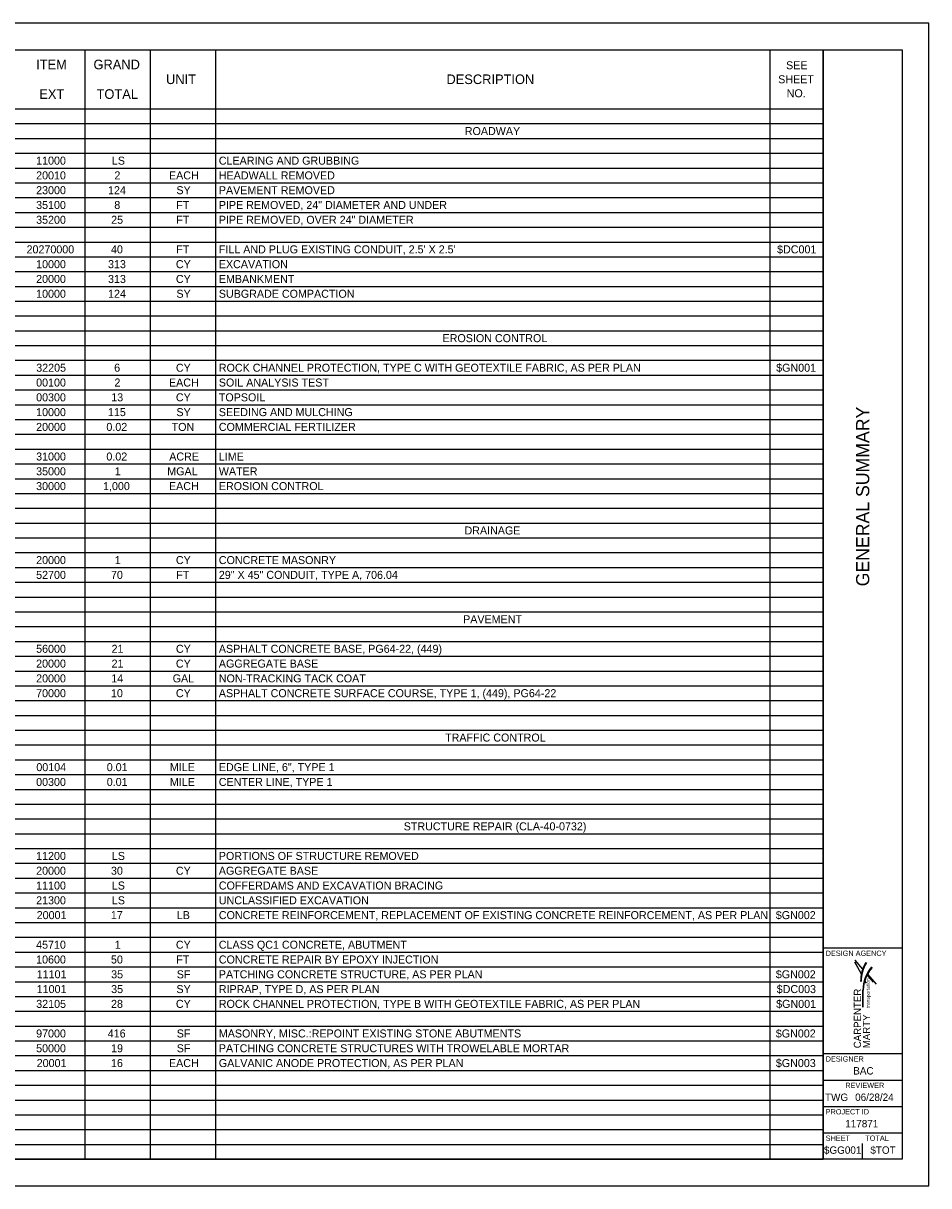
# Model space of a CAD drawing. Extents: x 0 to 34, y 0 to 22.
# Drawn here: x 16.87 to 34, y 0 to 22 of the extents above; entities that cross this region are included whole.
import ezdxf

# ---------------------------------------------------------------- set-up
doc = ezdxf.new("R2010")
doc.units = 0
for name, color, linetype in [('SH_Border', 7, 'Continuous'), ('SH_Cut_Line', 7, 'Continuous'), ('SH_Data', 7, 'Continuous'), ('SH_Text', 7, 'Continuous')]:
    doc.layers.add(name, color=color, linetype=linetype)

msp = doc.modelspace()

# ---------------------------------------------------------------- linework, layer by layer
at = {"layer": 'SH_Border'}
for p, q in [((32, 0.5), (32, 21.5)), ((32, 4.5), (33.5, 4.5)), ((32, 2.5), (33.5, 2.5)), ((32, 2), (33.5, 2)), ((32, 1.5), (33.5, 1.5)), ((32, 1), (33.5, 1))]:
    msp.add_line(p, q, dxfattribs=at)
msp.add_lwpolyline([(1.5, 21.5), (33.5, 21.5), (33.5, 0.5), (1.5, 0.5)], close=True, dxfattribs=at)
at = {"layer": 'SH_Cut_Line'}
msp.add_lwpolyline([(0, 0), (34, 0), (34, 22), (0, 22)], close=True, dxfattribs=at)
at = {"layer": 'SH_Data'}
for p, q in [((32.75, 3.5), (32.75, 3.5)), ((32.375, 0.675), (32.375, 0.675)), ((32.75, 0.5), (32.75, 0.8))]:
    msp.add_line(p, q, dxfattribs=at)
at = {"layer": 'SH_Text'}
for p, q in [((1.5, 21.5), (32, 21.5)), ((18.035, 21.5), (18.035, 0.502)), ((19.27, 21.5), (19.27, 0.502)), ((20.505, 21.5), (20.505, 0.502)), ((30.995, 21.5), (30.995, 0.502)), ((32, 21.5), (32, 0.502)), ((1.5, 20.38), (32, 20.38)), ((1.5, 20.1), (32, 20.1)), ((1.5, 19.82), (32, 19.82)), ((1.5, 19.54), (32, 19.54)), ((1.5, 19.26), (32, 19.26)), ((1.5, 18.98), (32, 18.98)), ((1.5, 18.7), (32, 18.7)), ((1.5, 18.42), (32, 18.42)), ((1.5, 18.14), (32, 18.14)), ((1.5, 17.86), (32, 17.86)), ((1.5, 17.58), (32, 17.58)), ((1.5, 17.3), (32, 17.3)), ((1.5, 17.021), (32, 17.021)), ((1.5, 16.741), (32, 16.741)), ((1.5, 16.461), (32, 16.461)), ((1.5, 16.181), (32, 16.181)), ((1.5, 15.901), (32, 15.901)), ((1.5, 15.621), (32, 15.621)), ((1.5, 15.341), (32, 15.341)), ((1.5, 15.061), (32, 15.061)), ((1.5, 14.781), (32, 14.781)), ((1.5, 14.501), (32, 14.501)), ((1.5, 14.221), (32, 14.221)), ((1.5, 13.941), (32, 13.941)), ((1.5, 13.661), (32, 13.661)), ((1.5, 13.381), (32, 13.381)), ((1.5, 13.101), (32, 13.101)), ((1.5, 12.821), (32, 12.821)), ((1.5, 12.541), (32, 12.541)), ((1.5, 12.261), (32, 12.261)), ((1.5, 11.981), (32, 11.981)), ((1.5, 11.701), (32, 11.701)), ((1.5, 11.421), (32, 11.421)), ((1.5, 11.141), (32, 11.141)), ((1.5, 10.861), (32, 10.861)), ((1.5, 10.581), (32, 10.581)), ((1.5, 10.301), (32, 10.301)), ((1.5, 10.021), (32, 10.021)), ((1.5, 9.741), (32, 9.741)), ((1.5, 9.461), (32, 9.461)), ((1.5, 9.181), (32, 9.181)), ((1.5, 8.901), (32, 8.901)), ((1.5, 8.621), (32, 8.621)), ((1.5, 8.342), (32, 8.342)), ((1.5, 8.062), (32, 8.062)), ((1.5, 7.782), (32, 7.782)), ((1.5, 7.502), (32, 7.502)), ((1.5, 7.222), (32, 7.222)), ((1.5, 6.942), (32, 6.942)), ((1.5, 6.662), (32, 6.662)), ((1.5, 6.382), (32, 6.382)), ((1.5, 6.102), (32, 6.102)), ((1.5, 5.822), (32, 5.822)), ((1.5, 5.542), (32, 5.542)), ((1.5, 5.262), (32, 5.262)), ((1.5, 4.982), (32, 4.982)), ((1.5, 4.702), (32, 4.702)), ((1.5, 4.422), (32, 4.422)), ((32.721, 4.016), (32.602, 4.232)), ((1.5, 4.142), (32, 4.142)), ((32.952, 3.853), (32.834, 3.991)), ((32.839, 4.002), (33.006, 3.816)), ((1.5, 3.862), (32, 3.862)), ((32.811, 3.84), (32.79, 3.88)), ((32.82, 3.834), (32.791, 3.886)), ((1.5, 3.582), (32, 3.582)), ((32.755, 3.378), (32.755, 3.704)), ((32.762, 3.378), (32.762, 3.704)), ((1.5, 3.302), (32, 3.302)), ((1.5, 3.022), (32, 3.022)), ((1.5, 2.742), (32, 2.742)), ((1.5, 2.462), (32, 2.462)), ((1.5, 2.182), (32, 2.182)), ((1.5, 1.902), (32, 1.902)), ((1.5, 1.622), (32, 1.622)), ((1.5, 1.342), (32, 1.342)), ((1.5, 1.062), (32, 1.062)), ((1.5, 0.782), (32, 0.782)), ((1.5, 0.502), (32, 0.502))]:
    msp.add_line(p, q, dxfattribs=at)
for points in [[(32.746, 4.104), (32.601, 4.266)], [(32.601, 4.266), (32.744, 4.098)], [(32.721, 4.016), (32.602, 4.232)], [(32.602, 4.232), (32.719, 4.011)]]:
    msp.add_lwpolyline(points, dxfattribs=at)
for centre, radius, start, end in [((33.432, 3.86), 0.721, 149.5704, 179.5529), ((33.373, 3.862), 0.654, 147.1423, 179.6525), ((33.426, 3.704), 0.671, 139.2898, 180.0106), ((33.433, 3.688), 0.672, 138.5126, 178.6075)]:
    msp.add_arc(centre, radius, start, end, dxfattribs=at)

# ---------------------------------------------------------------- texts
at = {"layer": 'SH_Data'}
msp.add_text('GENERAL SUMMARY', height=0.25, rotation=90, dxfattribs=at).set_placement((32.875, 11.344))
for s, height, p in [('DESIGN AGENCY', 0.1, (32.05, 4.35)), ('DESIGNER', 0.1, (32.05, 2.35)), ('BAC', 0.14, (32.572, 2.105)), ('REVIEWER', 0.1, (32.422, 1.85)), ('TWG', 0.14, (32.038, 1.605)), ('06/28/24', 0.14, (32.608, 1.605)), ('PROJECT ID', 0.1, (32.05, 1.35)), ('117871', 0.14, (32.421, 1.105)), ('SHEET', 0.1, (32.05, 0.85)), ('TOTAL', 0.1, (32.8, 0.85)), ('$GG001', 0.14, (32.018, 0.605)), ('$TOT', 0.14, (32.896, 0.605))]:
    msp.add_text(s, height=height, dxfattribs=at).set_placement(p)
at = {"layer": 'SH_Text'}
for s, height, p in [('ITEM', 0.1818, (17.115, 21.129)), ('GRAND', 0.1818, (18.2, 21.129)), ('SEE ', 0.1515, (31.301, 21.129)), ('UNIT', 0.1818, (19.573, 20.849)), ('DESCRIPTION', 0.18181, (24.877, 20.849)), ('SHEET ', 0.1515, (31.152, 20.864)), ('EXT', 0.1818, (17.175, 20.569)), ('TOTAL', 0.1818, (18.258, 20.569)), ('NO.', 0.1515, (31.313, 20.599)), ('ROADWAY', 0.1515, (25.224, 19.884)), ('11000', 0.1515, (17.115, 19.324)), ('LS', 0.1515, (18.548, 19.324)), ('CLEARING AND GRUBBING', 0.15151, (20.571, 19.324)), ('20010', 0.1515, (17.115, 19.045)), ('2', 0.152, (18.596, 19.045)), ('EACH', 0.1515, (19.628, 19.045)), ('HEADWALL REMOVED', 0.15151, (20.571, 19.045)), ('23000', 0.1515, (17.115, 18.765)), ('124', 0.1515, (18.475, 18.765)), ('SY', 0.1515, (19.769, 18.765)), ('PAVEMENT REMOVED', 0.15151, (20.571, 18.765)), ('35100', 0.1515, (17.115, 18.485)), ('8', 0.152, (18.593, 18.485)), ('FT', 0.1515, (19.766, 18.485)), ('PIPE REMOVED, 24" DIAMETER AND UNDER', 0.15151, (20.571, 18.485)), ('35200', 0.1515, (17.115, 18.205)), ('25', 0.1515, (18.534, 18.205)), ('FT', 0.1515, (19.766, 18.205)), ('PIPE REMOVED, OVER 24" DIAMETER', 0.15151, (20.571, 18.205)), ('20270000', 0.1515, (16.934, 17.645)), ('40', 0.1515, (18.531, 17.645)), ('FT', 0.1515, (19.766, 17.645)), ("FILL AND PLUG EXISTING CONDUIT, 2.5' X 2.5'", 0.15151, (20.571, 17.645)), ('$DC001', 0.1515, (31.131, 17.645)), ('10000', 0.1515, (17.115, 17.365)), ('313', 0.1515, (18.475, 17.365)), ('CY', 0.1515, (19.759, 17.365)), ('EXCAVATION', 0.1515, (20.571, 17.365)), ('20000', 0.1515, (17.115, 17.085)), ('313', 0.1515, (18.475, 17.085)), ('CY', 0.1515, (19.759, 17.085)), ('EMBANKMENT', 0.1515, (20.571, 17.085)), ('10000', 0.1515, (17.115, 16.805)), ('124', 0.1515, (18.475, 16.805)), ('SY', 0.1515, (19.769, 16.805)), ('SUBGRADE COMPACTION', 0.15151, (20.571, 16.805)), ('EROSION CONTROL', 0.15151, (24.803, 15.965)), ('32205', 0.1515, (17.117, 15.405)), ('6', 0.152, (18.591, 15.405)), ('CY', 0.1515, (19.759, 15.405)), ('ROCK CHANNEL PROTECTION, TYPE C WITH GEOTEXTILE FABRIC, AS PER PLAN', 0.15151, (20.571, 15.405)), ('$GN001', 0.1515, (31.114, 15.405)), ('00100', 0.1515, (17.115, 15.125)), ('2', 0.152, (18.596, 15.125)), ('EACH', 0.1515, (19.628, 15.125)), ('SOIL ANALYSIS TEST', 0.15151, (20.571, 15.125)), ('00300', 0.1515, (17.115, 14.845)), ('13', 0.1515, (18.536, 14.845)), ('CY', 0.1515, (19.759, 14.845)), ('TOPSOIL', 0.1515, (20.571, 14.845)), ('10000', 0.1515, (17.115, 14.565)), ('115', 0.1515, (18.473, 14.565)), ('SY', 0.1515, (19.769, 14.565)), ('SEEDING AND MULCHING', 0.15151, (20.571, 14.565)), ('20000', 0.1515, (17.115, 14.285)), ('0.02', 0.1515, (18.444, 14.285)), ('TON', 0.1515, (19.678, 14.285)), ('COMMERCIAL FERTILIZER', 0.15151, (20.571, 14.285)), ('31000', 0.1515, (17.115, 13.725)), ('0.02', 0.1515, (18.444, 13.725)), ('ACRE', 0.1515, (19.633, 13.725)), ('LIME', 0.1515, (20.571, 13.725)), ('35000', 0.1515, (17.115, 13.445)), ('1', 0.152, (18.603, 13.445)), ('MGAL', 0.1515, (19.596, 13.445)), ('WATER', 0.1515, (20.571, 13.445)), ('30000', 0.1515, (17.115, 13.165)), ('1,000', 0.1515, (18.381, 13.165)), ('EACH', 0.1515, (19.628, 13.165)), ('EROSION CONTROL', 0.15151, (20.571, 13.165)), ('DRAINAGE', 0.1515, (25.218, 12.325)), ('20000', 0.1515, (17.115, 11.765)), ('1', 0.152, (18.603, 11.765)), ('CY', 0.1515, (19.759, 11.765)), ('CONCRETE MASONRY', 0.15151, (20.571, 11.765)), ('52700', 0.1515, (17.115, 11.485)), ('70', 0.1515, (18.531, 11.485)), ('FT', 0.1515, (19.766, 11.485)), ('29" X 45" CONDUIT, TYPE A, 706.04', 0.15151, (20.571, 11.485)), ('PAVEMENT', 0.1515, (25.192, 10.645)), ('56000', 0.1515, (17.115, 10.086)), ('21', 0.1515, (18.542, 10.086)), ('CY', 0.1515, (19.759, 10.086)), ('ASPHALT CONCRETE BASE, PG64-22, (449)', 0.15151, (20.571, 10.086)), ('20000', 0.1515, (17.115, 9.806)), ('21', 0.1515, (18.542, 9.806)), ('CY', 0.1515, (19.759, 9.806)), ('AGGREGATE BASE', 0.15151, (20.571, 9.806)), ('20000', 0.1515, (17.115, 9.526)), ('14', 0.1515, (18.536, 9.526)), ('GAL', 0.1515, (19.698, 9.526)), ('NON-TRACKING TACK COAT', 0.15151, (20.571, 9.526)), ('70000', 0.1515, (17.115, 9.246)), ('10', 0.1515, (18.531, 9.246)), ('CY', 0.1515, (19.759, 9.246)), ('ASPHALT CONCRETE SURFACE COURSE, TYPE 1, (449), PG64-22', 0.15151, (20.571, 9.246)), ('TRAFFIC CONTROL', 0.15151, (24.851, 8.406)), ('00104', 0.1515, (17.119, 7.846)), ('0.01', 0.1515, (18.451, 7.846)), ('MILE', 0.1515, (19.645, 7.846)), ('EDGE LINE, 6", TYPE 1', 0.15151, (20.571, 7.846)), ('00300', 0.1515, (17.115, 7.566)), ('0.01', 0.1515, (18.451, 7.566)), ('MILE', 0.1515, (19.645, 7.566)), ('CENTER LINE, TYPE 1', 0.15151, (20.571, 7.566)), ('STRUCTURE REPAIR (CLA-40-0732)', 0.15151, (24.068, 6.726)), ('11200', 0.1515, (17.115, 6.166)), ('LS', 0.1515, (18.548, 6.166)), ('PORTIONS OF STRUCTURE REMOVED', 0.15151, (20.571, 6.166)), ('20000', 0.1515, (17.115, 5.886)), ('30', 0.1515, (18.531, 5.886)), ('CY', 0.1515, (19.759, 5.886)), ('AGGREGATE BASE', 0.15151, (20.571, 5.886)), ('11100', 0.1515, (17.115, 5.606)), ('LS', 0.1515, (18.548, 5.606)), ('COFFERDAMS AND EXCAVATION BRACING', 0.15151, (20.571, 5.606)), ('21300', 0.1515, (17.115, 5.326)), ('LS', 0.1515, (18.548, 5.326)), ('UNCLASSIFIED EXCAVATION', 0.15151, (20.571, 5.326)), ('20001', 0.1515, (17.126, 5.046)), ('17', 0.1515, (18.528, 5.046)), ('LB', 0.1515, (19.776, 5.046)), ('CONCRETE REINFORCEMENT, REPLACEMENT OF EXISTING CONCRETE REINFORCEMENT, AS PER PLAN', 0.15151, (20.571, 5.046)), ('$GN002', 0.1515, (31.107, 5.046)), ('45710', 0.1515, (17.115, 4.486)), ('1', 0.152, (18.603, 4.486)), ('CY', 0.1515, (19.759, 4.486)), ('CLASS QC1 CONCRETE, ABUTMENT', 0.15151, (20.571, 4.486)), ('10600', 0.1515, (17.115, 4.206)), ('50', 0.1515, (18.531, 4.206)), ('FT', 0.1515, (19.766, 4.206)), ('CONCRETE REPAIR BY EPOXY INJECTION', 0.15151, (20.571, 4.206)), ('11101', 0.1515, (17.126, 3.926)), ('35', 0.1515, (18.534, 3.926)), ('SF', 0.1515, (19.775, 3.926)), ('PATCHING CONCRETE STRUCTURE, AS PER PLAN', 0.15151, (20.571, 3.926)), ('$GN002', 0.1515, (31.107, 3.926)), ('11001', 0.1515, (17.126, 3.646)), ('35', 0.1515, (18.534, 3.646)), ('SY', 0.1515, (19.769, 3.646)), ('RIPRAP, TYPE D, AS PER PLAN', 0.15151, (20.571, 3.646)), ('$DC003', 0.1515, (31.124, 3.646)), ('32105', 0.1515, (17.117, 3.366)), ('28', 0.1515, (18.532, 3.366)), ('CY', 0.1515, (19.759, 3.366)), ('ROCK CHANNEL PROTECTION, TYPE B WITH GEOTEXTILE FABRIC, AS PER PLAN', 0.15151, (20.571, 3.366)), ('$GN001', 0.1515, (31.114, 3.366)), ('97000', 0.1515, (17.115, 2.806)), ('416', 0.1515, (18.47, 2.806)), ('SF', 0.1515, (19.775, 2.806)), ('MASONRY, MISC.:REPOINT EXISTING STONE ABUTMENTS', 0.15151, (20.571, 2.806)), ('$GN002', 0.1515, (31.107, 2.806)), ('50000', 0.1515, (17.115, 2.526)), ('19', 0.1515, (18.533, 2.526)), ('SF', 0.1515, (19.775, 2.526)), ('PATCHING CONCRETE STRUCTURES WITH TROWELABLE MORTAR', 0.15151, (20.571, 2.526)), ('20001', 0.1515, (17.126, 2.246)), ('16', 0.1515, (18.531, 2.246)), ('EACH', 0.1515, (19.628, 2.246)), ('GALVANIC ANODE PROTECTION, AS PER PLAN', 0.15151, (20.571, 2.246)), ('$GN003', 0.1515, (31.108, 2.246))]:
    msp.add_text(s, height=height, dxfattribs=at).set_placement(p)
for s, height, p in [('transportation', 0.06649, (32.885, 3.364)), ('CARPENTER ', 0.1367, (32.719, 2.602)), ('MARTY', 0.1367, (32.891, 2.602))]:
    msp.add_text(s, height=height, rotation=90, dxfattribs=at).set_placement(p)

doc.saveas('drawing.dxf')
